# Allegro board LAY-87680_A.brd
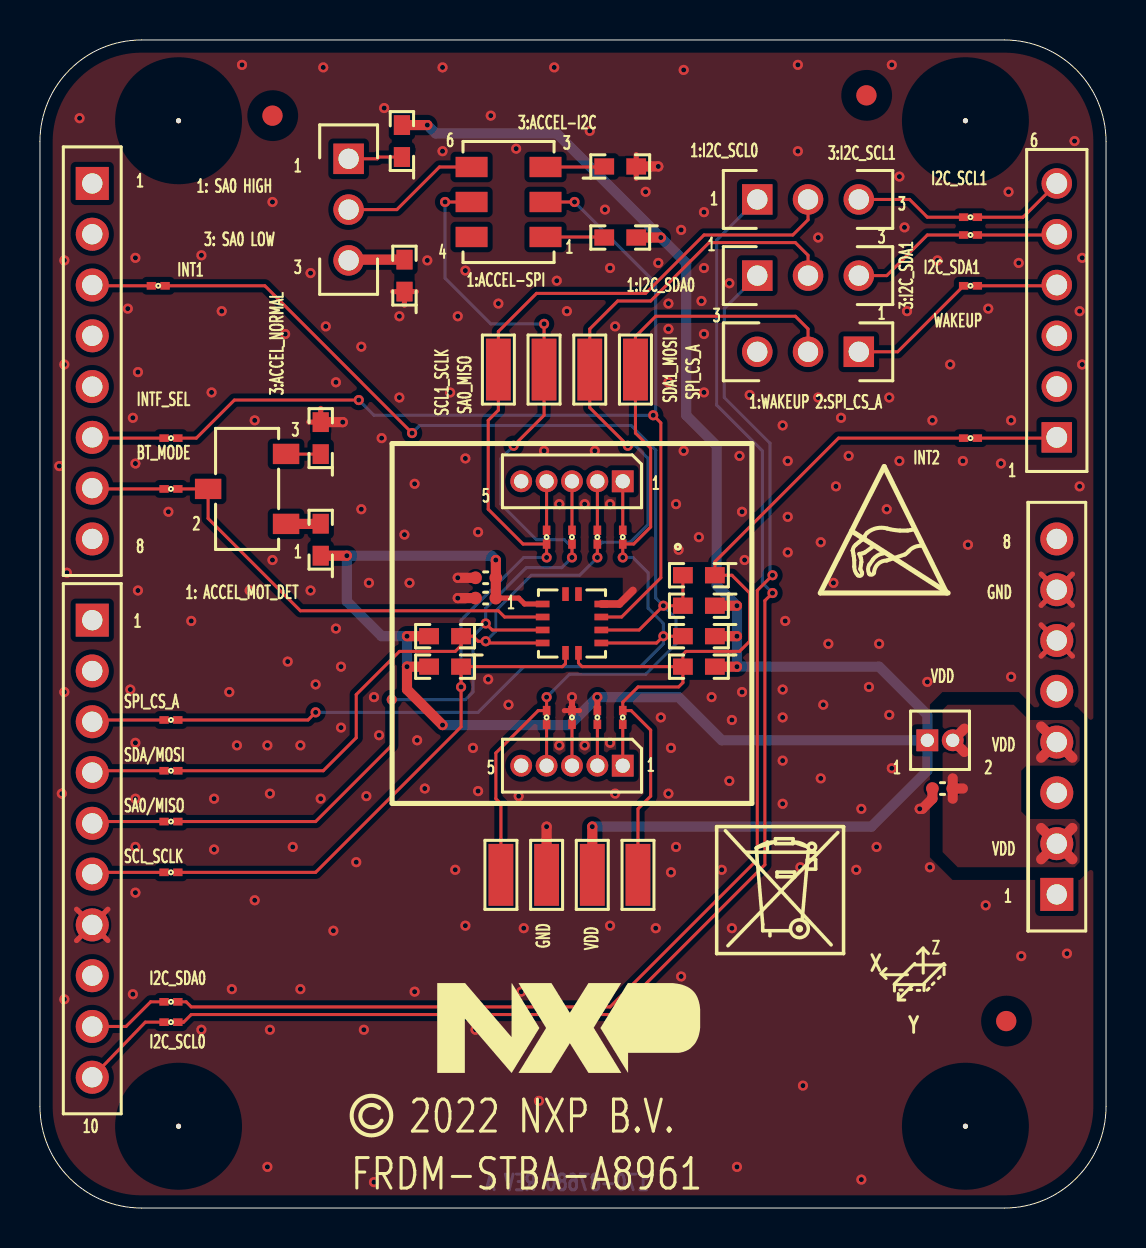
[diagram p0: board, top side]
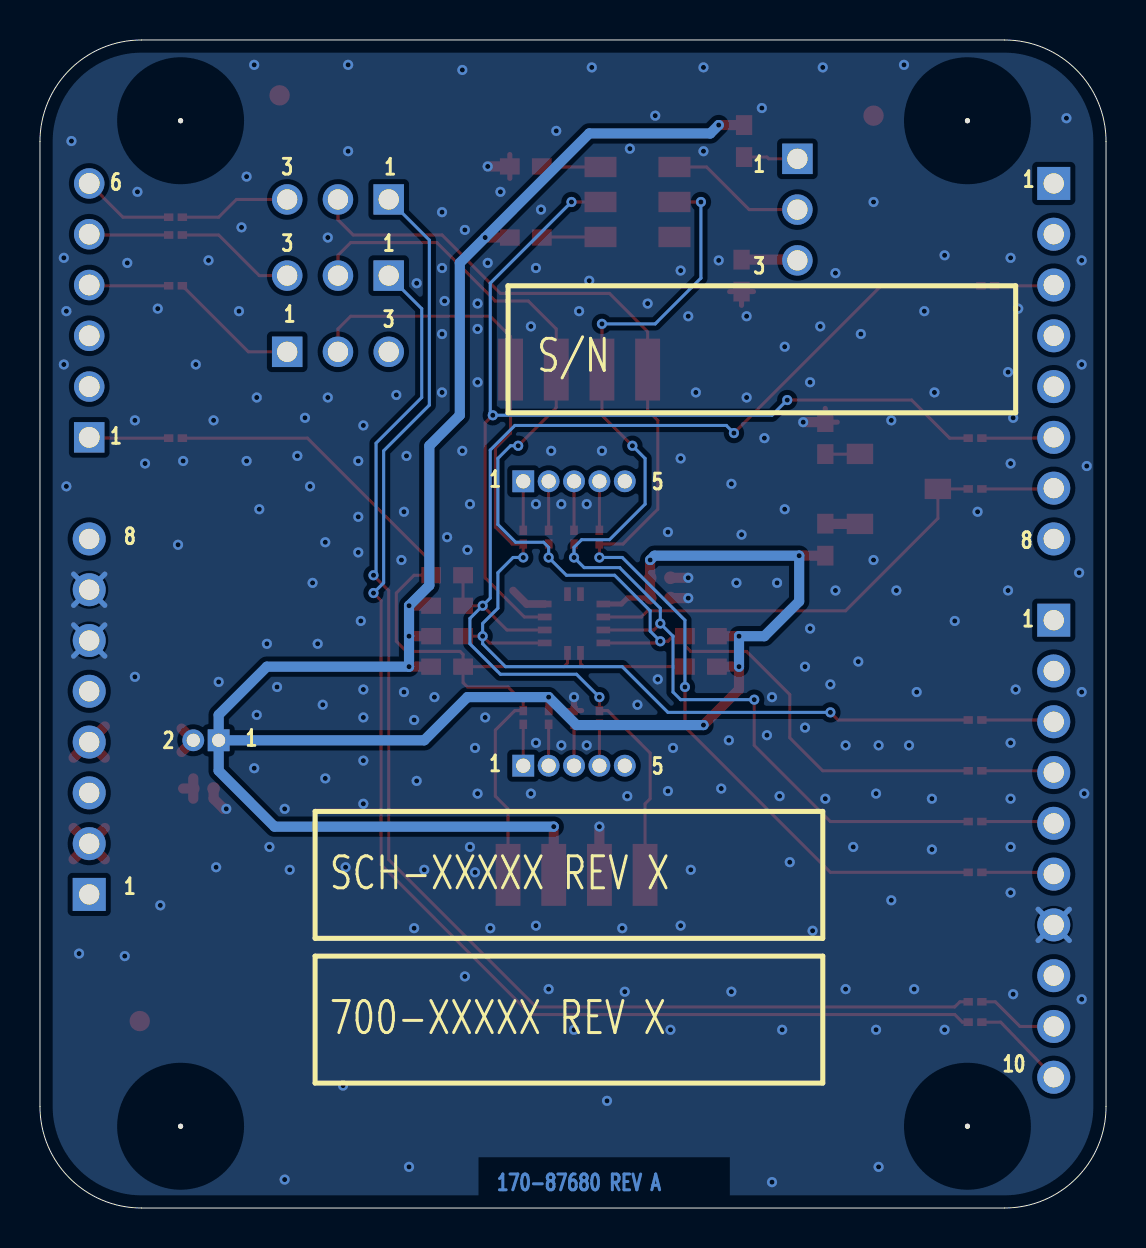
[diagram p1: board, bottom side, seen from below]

Outline 53.34 x 58.42 mm; copper layers: TOP, BOTTOM. Coordinates in mm from the lower left corner of the outline.
Outline path: 0,53.34 0,5.08 arc(1.49,1.49) 5.08,0 48.26,0 arc(51.85,1.49) 53.34,5.08 53.34,53.34 arc(51.85,56.93) 48.26,58.42 5.08,58.42 arc(1.49,56.93) 0,53.34

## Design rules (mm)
constraint set DEFAULT: min track width 0.152
net group BT_MODE: nets BT_MODE N16720548
net group I2C_SCL0: nets I2C_SCL0 N00628
net group I2C_SCL1: nets I2C_SCL1 N05692
net group I2C_SDA0: nets I2C_SDA0 N00622
net group I2C_SDA1: nets I2C_SDA1 N05729
net group INTF_SEL: nets INTF_SEL N16720544
net group WAKEUP: nets N16721741 WAKEUP
net group INT2: nets INT1 INT2 N16659634 N16701284 N16711839 N16711845
net group SA0_MISO: nets N16652885 N16711875 SA0_MISO
net group SCL1_SCLK: nets N16652889 N16711877 SCL1_SCLK
net group SDA1_MOSI: nets N16652859 N16711873 SDA1_MOSI
net group SPI_CS_A: nets N16653001 N16711871 SPI_CS_A

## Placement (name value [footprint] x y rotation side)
C4  0.1UF  [CC0402_25]  22.3 30.51 180 top
C5  1.0UF  [CC0402_25]  22.3 31.52 180 top
C16  2.2UF  [CC0402_25]  45.16 20.98 180 top
INT1  0805  [TESTPOINT_122X049MIL]  23.06 16.66 90 top
INT2  0805  [TESTPOINT_122X049MIL]  29.92 16.66 90 top
J1  HDR 1X5  [HDR1X5_50_TH]  29.16 36.35 0 top
J2  HDR 1X5  [HDR1X5_50_TH]  29.16 22.12 0 top
J3  SKT_1X8  [CON_SKT1X8_TH]  2.62 51.24 0 top
J4  SKT_1X6  [CON_SKT1X6_TH]  50.88 38.54 180 top
J5  SKT_1X10  [CON_SKT1X10_TH]  2.62 29.4 0 top
J6  SKT_1X8  [CON_SKT1X8_TH]  50.88 15.68 180 top
J7  HDR TH 1X3  [HDR103]  35.89 46.63 90 top
J8  HDR TH 1X3  [HDR103]  35.89 50.44 90 top
J9  HDR TH 1X3  [HDR103]  40.97 42.82 270 top
J10  HDR 1X2  [HDR1X2_1P27_TH]  44.4 23.39 180 top
J11  HDR TH 1X3  [HDR103]  15.44 52.48 0 top
NOREF  -  [unnamed]  48.35 9.35 180 top
NOREF#2  -  [unnamed]  11.63 54.64 180 top
NOREF#3  -  [#2]  -142.22 -0.67 0 top
NOREF#4  -  [#2]  44.4 23.39 0 top
NOREF#5  -  [#2]  -142.22 0.62 90 top
NOREF#6  -  [#2]  -125.2 -14.62 90 top
NOREF#7  -  [#2]  -125.2 5.7 90 top
NOREF#8  -  [#2]  6.45 2.61 0 top
NOREF#9  -  [#2]  -142.22 1.87 0 top
NOREF#10  -  [#2]  -142.22 5.7 90 top
NOREF#11  -  [#2]  -132.38 2.56 90 top
NOREF#12  -  [unnamed]  46.3 54.38 0 top
NOREF#13  -  [#2]  27.89 36.35 0 top
NOREF#14  -  [#2]  52.79 55.63 0 top
NOREF#15  -  [#2]  -131.61 2.84 90 top
NOREF#16  -  [#2]  -125.2 6.95 0 top
NOREF#17  -  [#2]  -142.22 -8.29 0 top
NOREF#18  -  [#2]  -142.22 -14.62 90 top
NOREF#19  -  [#2]  -125.2 -12.08 90 top
NOREF#20  -  [#2]  -142.22 -1.92 90 top
NOREF#21  -  [#2]  -431.98 245.39 0 top
NOREF#22  -  [#2]  -134.38 2.34 0 top
NOREF#23  -  [#2]  29.17 42.94 0 top
NOREF#24  -  [#2]  -142.22 -9.54 90 top
NOREF#25  -  [#2]  -142.22 4.41 0 top
NOREF#26  -  [#2]  43.74 24.68 0 top
NOREF#27  -  [#2]  23.56 40.94 90 top
NOREF#28  -  [#2]  30.42 40.94 90 top
NOREF#29  -  [#2]  -125.2 -13.37 0 top
NOREF#30  -  [#2]  -125.2 3.16 90 top
NOREF#31  -  [#2]  16.71 20.98 90 top
NOREF#32  -  [unnamed]  41.35 55.65 180 top
NOREF#33  -  [#2]  -142.22 -3.21 0 top
NOREF#34  -  [#2]  16.71 35.2 90 top
NOREF#35  -  [#2]  16.71 35.2 0 top
NOREF#36  -  [#2]  26.88 42.94 0 top
NOREF#37  -  [#2]  -142.22 -7 90 top
NOREF#38  -  [#2]  27.01 17.66 0 top
NOREF#39  -  [#2]  -125.2 -0.67 0 top
NOREF#40  -  [#2]  -131.61 2.84 90 top
NOREF#41  -  [#2]  44.05 7.77 0 top
NOREF#42  -  [#2]  -125.2 0.62 90 top
NOREF#43  -  [#2]  -125.2 -9.54 90 top
NOREF#44  -  [#2]  -131.4 5.34 0 top
NOREF#45  -  [#2]  22.31 42.94 0 top
NOREF#46  -  [#2]  46.48 0 90 top
NOREF#47  -  [#2]  -125.2 -5.75 0 top
NOREF#48  -  [#2]  28.13 40.94 90 top
NOREF#49  -  [unnamed]  6.93 54.38 0 top
NOREF#50  -  [#2]  -131.61 2.84 90 top
NOREF#51  -  [#2]  -125.2 -7 90 top
NOREF#52  -  [#2]  -142.22 -12.08 90 top
NOREF#53  -  [#2]  -142.22 -4.46 90 top
NOREF#54  -  [#2]  -142.22 -10.83 0 top
NOREF#55  -  [#2]  22.44 17.66 0 top
NOREF#56  -  [#2]  17.62 38.24 0 top
NOREF#57  -  [#2]  29.3 17.66 0 top
NOREF#58  -  [#2]  -142.22 6.95 0 top
NOREF#59  -  [#2]  -142.22 -13.37 0 top
NOREF#60  -  [#2]  23.69 15.66 90 top
NOREF#61  -  [#2]  -125.2 1.87 0 top
NOREF#62  -  [#2]  -125.2 -3.21 0 top
NOREF#63  -  [unnamed]  6.93 4.09 0 top
NOREF#64  -  [#2]  17.62 20.24 90 top
NOREF#65  -  [#2]  -142.22 -5.75 0 top
NOREF#66  -  [#2]  30.55 15.66 90 top
NOREF#67  -  [#2]  -125.2 -4.46 90 top
NOREF#68  -  [#2]  39.07 30.76 0 top
NOREF#69  -  [#2]  27.89 22.12 0 top
NOREF#70  -  [#2]  16.71 20.98 0 top
NOREF#71  -  [#2]  25.85 40.94 90 top
NOREF#72  -  [#2]  -25.42 -46.55 0 top
NOREF#73  -  [#2]  -131.38 2.34 90 top
NOREF#74  -  [#2]  19.89 6.76 0 top
NOREF#75  -  [#2]  0 52.62 0 top
NOREF#76  -  [#2]  -125.2 4.41 0 top
NOREF#77  -  [#2]  -134.16 2.84 0 top
NOREF#78  -  [#2]  -125.2 -1.92 90 top
NOREF#79  -  [#2]  -142.22 3.16 90 top
NOREF#80  -  [#2]  24.6 42.94 0 top
NOREF#81  -  [#2]  25.97 15.66 90 top
NOREF#82  -  [#2]  -458.69 -278.74 0 top
NOREF#83  -  [#2]  -133.38 2.56 0 top
NOREF#84  -  [#2]  24.72 17.66 0 top
NOREF#85  -  [#2]  -125.2 -8.29 0 top
NOREF#86  -  [#2]  28.26 15.66 90 top
NOREF#87  -  [#2]  16.59 4.6 0 top
NOREF#88  -  [unnamed]  46.3 4.09 0 top
NOREF#89  -  [#2]  -125.2 -10.83 0 top
NOREF#90  -  [#2]  -133.38 2.56 90 top
NOREF#91  -  [#2]  33.86 12.73 0 top
NOREF#92  -  [#2]  29.92 39.78 180 bottom
NOREF#93  -  [#2]  39.57 6.25 180 bottom
NOREF#94  -  [#2]  39.57 13.49 180 bottom
R1  4.7K  [RC0603]  20.27 27.08 180 top
R3  4.7K  [RC0603]  20.27 28.6 180 top
R4  10K  [RC0603]  32.97 28.6 180 top
R6  10K  [RC0603]  32.97 30.12 180 top
R9  10K  [RC0603]  32.97 27.08 180 top
R10  0  [RC0603]  32.97 31.65 180 top
R19  10K  [RC0603]  14.05 38.51 90 top
R20  10K  [RC0603]  14.05 33.43 90 top
R21  10K  [RC0603]  29.03 52.1 0 top
R24  10K  [RC0603]  29.03 48.54 180 top
R25  10K  [RC0603]  18.11 53.37 90 top
R26  10K  [RC0603]  18.24 46.63 90 top
SH1  0  [SH0201]  25.35 24.54 90 top
SH4  0  [SH0201]  27.89 24.54 90 top
SH5  0  [SH0201]  25.35 33.55 270 top
SH8  0  [SH0201]  29.16 33.55 270 top
SH9  0  [SH0201]  27.89 33.55 270 top
SH10  0  [SH0201]  29.16 24.54 90 top
SH11  0  [SH0201]  26.62 33.55 270 top
SH20  0  [SH0201]  26.62 24.54 90 top
SH21  0  [SH0201]  46.56 49.56 0 top
SH22  0  [SH0201]  5.92 46.13 0 top
SH23  0  [SH0201]  46.56 48.67 0 top
SH27  0  [SH0201]  46.56 38.51 0 top
SH30  0  [SH0201]  6.55 24.41 0 top
SH31  0  [SH0201]  6.55 21.87 0 top
SH32  0  [SH0201]  6.55 19.33 0 top
SH33  0  [SH0201]  6.55 16.79 0 top
SH34  0  [SH0201]  6.55 10.31 0 top
SH35  0  [SH0201]  6.55 9.3 0 top
SH37  0  [SH0201]  6.55 38.51 0 top
SH38  0  [SH0201]  6.55 35.97 0 top
SH39  0  [SH0201]  46.56 46.13 0 top
SW1  CAS-120TB  [SW3_1P75_3X6]  10.36 35.97 90 top
SW2  CAS-220TA  [SW6_1P75_4X5]  23.44 50.32 90 top
TP3  0805  [TESTPOINT_122X049MIL]  27.64 16.66 90 top
TP4  0805  [TESTPOINT_122X049MIL]  25.35 16.66 90 top
TP5  0805  [TESTPOINT_122X049MIL]  22.94 41.94 90 top
TP6  0805  [TESTPOINT_122X049MIL]  27.51 41.94 90 top
TP7  0805  [TESTPOINT_122X049MIL]  29.79 41.94 90 top
TP8  0805  [TESTPOINT_122X049MIL]  25.22 41.94 90 top
U1  FXLS8961AFR3  [QFN12_0P65_3X3]  26.62 29.24 0 top

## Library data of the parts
C4 C5 C16 = CAP_NP
INT1 INT2 TP3-TP8 = TEST_POINT
J1 J2 = CONN_HDR_5X1
J3 J6 = CONN_HDR_8X1
J4 = CONN_HDR_6X1
J5 = CONN_HDR_10X1
J7-J9 J11 = CONN_HDR_3X1
J10 = CONN_HDR_2X1
R1 R3 R4 R6 R9 R10 R19-R21 R24-R26 = RES
SH1 SH4 SH5 SH8-SH11 SH20-SH23 SH27 SH30-SH35 SH37-SH39 = RES_SHORT-2: Tolerance: TOLERANCE; User Part Number: 470-76473
SW1 = SW3_SPDT_SLD
SW2 = SW_SL_DPDT_6P
U1 = FXLS8961AFR3_QFN12

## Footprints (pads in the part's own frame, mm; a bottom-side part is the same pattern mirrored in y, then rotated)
CC0402_25
  round 0.635 smd: 1(-0.508,0) 2(0.508,0)
CON_SKT1X6_TH
  rect 1.524x1.524 hole 1.041: 1(0,0)
  round 1.524 hole 1.041: 2(0,-2.54) 3(0,-5.08) 4(0,-7.62) 5(0,-10.16) 6(0,-12.7)
CON_SKT1X8_TH
  rect 1.651x1.651 hole 1.016: 1(0,0)
  round 1.651 hole 1.016: 2(0,-2.54) 3(0,-5.08) 4(0,-7.62) 5(0,-10.16) 6(0,-12.7) 7(0,-15.24) 8(0,-17.78)
CON_SKT1X10_TH
  rect 1.651x1.651 hole 1.016: 1(0,0)
  round 1.651 hole 1.016: 2(0,-2.54) 3(0,-5.08) 4(0,-7.62) 5(0,-10.16) 6(0,-12.7) 7(0,-15.24) 8(0,-17.78) 9(0,-20.32) 10(0,-22.86)
HDR1X2_1P27_TH
  rect 1.092x1.092 hole 0.66: 1(0,0)
  round 1.092 hole 0.66: 2(-1.27,0)
HDR1X5_50_TH
  rect 1.092x1.092 hole 0.711: 1(0,0)
  round 1.092 hole 0.711: 2(-1.27,0) 3(-2.54,0) 4(-3.81,0) 5(-5.08,0)
HDR103
  rect 1.524x1.524 hole 1.016: 1(0,0)
  round 1.524 hole 1.016: 2(0,-2.54) 3(0,-5.08)
QFN12_0P65_3X3
  rect 0.686x0.33 smd: 1(-1.468,0.975) 2(-1.468,0.325) 3(-1.468,-0.325) 4(-1.468,-0.975) 7(1.468,-0.975) 8(1.468,-0.325) 9(1.468,0.325) 10(1.468,0.975)
  rect 0.33x0.686 smd: 5(-0.325,-1.468) 6(0.325,-1.468) 11(0.325,1.468) 12(-0.325,1.468)
RC0603
  rect 0.991x0.813 smd: 1(-0.8,0) 2(0.8,0)
SH0201
  rect 0.47x0.381 smd: 1(-0.343,0) 2(0.343,0)
SW3_1P75_3X6
  rect 1.016x1.321 smd: 1(-1.75,-1.95) 2(0,1.95) 3(1.75,-1.95)
SW6_1P75_4X5
  rect 1.016x1.6 smd: 1(-1.75,-1.85) 2(0,-1.85) 3(1.75,-1.85) 4(-1.75,1.85) 5(0,1.85) 6(1.75,1.85)
TESTPOINT_122X049MIL
  rect 3.099x1.245 smd: 1(0,0)
unnamed
  round 1.016 smd: (0,0)

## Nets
GND: C4.2 C5.2 C16.2 J5.7 J6.6 J6.7 R19.2 R21.2 R26.1 SH20.2 TP4.1 U1.10
VDD: C4.1 C5.1 J10.1 R1.2 R3.2 R4.1 R6.1 R9.1 R20.1 R24.1 R25.2 SH4.2 TP3.1 U1.1
BT_MODE: SH38.2 SW1.2 U1.2
I2C_SCL0: J8.1 SH35.2
I2C_SCL1: J8.3 SH21.1
I2C_SDA0: J7.1 SH34.2
I2C_SDA1: J7.3 SH23.1
INT1: INT1.1 R6.2 R10.2 SH1.2 SH22.2 U1.8
INT2: INT2.1 R9.2 R10.1 SH10.2 SH27.1 U1.6
INTF_SEL: SH37.2 SW2.2 U1.9
SA0_MISO: SH11.2 SH32.2 SW2.5(\COM2\) TP8.1 U1.3
SCL1_SCLK: J8.2 R1.1 SH5.2 SH33.2 TP5.1 U1.5
SDA1_MOSI: J7.2 R3.1 SH9.2 SH31.2 TP6.1 U1.4
SPI_CS_A: J9.2 R4.2 SH8.2 SH30.2 TP7.1 U1.7(\\\S\\P\\I\\_\\C\\S\\/WAKE_UP\)
WAKEUP: J9.1 SH39.1
N00622: J5.9 SH34.1
N00628: J5.10 SH35.1
N00993: C16.1 J6.2 J6.4 J10.2
N05692: J4.6 SH21.2
N05729: J4.5 SH23.2
N16652859: J5.4 SH31.1
N16652885: J5.5 SH32.1
N16652889: J5.6 SH33.1
N16653001: J5.3 SH30.1
N16659634: J4.1 SH27.2
N16701284: J3.3 SH22.1
N16711839: J2.1 SH10.1
N16711841: J2.2 SH4.1
N16711843: J2.3 SH20.1
N16711845: J2.4 SH1.1
N16711871: J1.1 SH8.1
N16711873: J1.2 SH9.1
N16711875: J1.3 SH11.1
N16711877: J1.4 SH5.1
N16715705: R20.2 SW1.1
N16718521: R21.1 SW2.3
N16718681: R24.2 SW2.1
N16720544: J3.6 SH37.1
N16720548: J3.7 SH38.1
N16721741: J4.4 SH39.2
N16750160: J11.2 SW2.6
N16750243: J11.1 R25.1
N16750529: J11.3 R26.2
N16884640: R19.1 SW1.3

Pads without a net: J1 5; J2 5; J3 1 2 4 5 8; J4 2 3; J5 1 2 8; J6 1 3 5 8; J9 3; SW2 4; U1 11 12

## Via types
v1: diameter 0.508, hole 0.254, TOP to BOTTOM, 252 vias

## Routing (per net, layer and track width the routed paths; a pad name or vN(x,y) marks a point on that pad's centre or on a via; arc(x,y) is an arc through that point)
GND: length 41.9
  TOP w0.254: 1.83,14.94 J5.7 ; J5.7 1.83,13.38 ; J5.7 3.4,13.38 ; J5.7 3.4,14.94 ; 50.09,27.6 J6.6 ; J6.6 51.66,27.6 ; J6.6 51.66,29.17 ; J6.6 50.09,29.17 ; 27,24.88 SH20.2 26.24,24.88 ; 13.45,39.31 R19.2 14.05,39.99 ; 50.09,30.14 J6.7 ; J6.7 51.66,31.71 ; J6.7 50.09,31.71 ; J6.7 51.66,30.14 ; 17.64,45.83 R26.1 ; R26.1 18.24,45.15 ; R26.1 18.83,45.83 ; 29.83,52.69 R21.2 29.83,51.5
  TOP w0.305: SH20.2 v1(26.62,25.55)
  TOP w0.381: 29.67,30.89 28.99,30.21 U1.10
  TOP w0.508: TP4.1 v1(25.35,19.08) ; C5.2 v1(20.9,31.52) ; v1(44.02,19.96) 44.15,19.96 44.65,20.47 44.65,20.98 ; C4.2 v1(20.9,30.51) ; R21.2 v1(30.94,52.1) ; R19.2 v1(15.15,39.31)
  BOTTOM w0.254: J6.7 51.66,31.71 ; J6.7 51.66,30.14 ; J6.7 50.09,31.71 ; J6.7 50.09,30.14 ; 1.83,14.94 J5.7 ; J5.7 3.4,14.94 ; J5.7 1.83,13.38 ; J5.7 3.4,13.38 ; J6.6 51.66,29.17 ; J6.6 50.09,27.6 ; J6.6 50.09,29.17 ; J6.6 51.66,27.6
  vias: v1(0.97,37.11) v1(1.09,20.73) v1(1.22,47.4) v1(1.22,42.19) v1(1.22,25.81) v1(1.22,10.44) v1(1.35,31.78) v1(1.98,54.51) v1(4.39,44.98) v1(4.52,25.93) v1(4.65,39.52) v1(4.65,10.69) v1(4.78,47.52) v1(4.78,37.24) v1(4.78,23.27) v1(4.78,20.47) v1(4.78,18.06) v1(4.78,15.77) v1(4.9,41.81) v1(4.9,30.89) v1(6.43,34.82) v1(7.57,29.36) v1(8.08,47.65) v1(8.08,8.92) v1(8.59,40.79) v1(8.71,20.47) v1(8.71,17.93) v1(9.09,44.86) v1(9.47,25.81) v1(9.6,10.95) v1(9.86,23.14) v1(10.11,57.18) v1(10.49,30.89) v1(10.74,39.4) v1(10.74,15.39) v1(11.38,23.14) v1(11.38,2.06) v1(11.51,20.73) v1(11.51,8.92) v1(11.63,50.32) v1(11.63,32.41) v1(12.27,43.71) v1(12.4,27.33) v1(12.65,18.06) v1(13.03,23.14) v1(13.03,10.95) v1(13.54,46.76) v1(13.54,30.89) v1(13.79,26.19) v1(14.05,20.47) v1(14.17,57.05) v1(14.3,44.09) v1(14.68,13.87) v1(14.81,41.3) v1(14.81,28.98) v1(15.06,27.08) v1(15.06,24.03) v1(15.82,17.3) v1(16.08,43.08) v1(16.08,34.95) v1(16.21,8.92) v1(16.33,20.6) v1(16.46,31.27) v1(16.71,25.55) v1(16.71,1.3) v1(16.97,23.65) v1(17.09,38.51) v1(17.22,55.02) v1(17.98,44.6) v1(17.98,40.54) v1(18.24,33.68) v1(18.49,31.27) v1(18.75,36.22) v1(18.75,10.82) v1(18.87,23.39) v1(19.25,20.98) v1(19.38,47.4) v1(20.14,57.05) v1(20.14,52.86) v1(20.52,40.79) v1(20.78,16.92) v1(20.9,44.6) v1(21.29,46.89) v1(21.29,37.49) v1(21.29,14.12) v1(21.67,23.01) v1(21.79,8.92) v1(21.92,33.81) v1(21.92,20.85) v1(22.43,26.44) v1(22.56,54.64) v1(22.94,45.24) v1(23.44,25.17) v1(23.83,52.98) v1(23.95,20.6) v1(24.08,10.82) v1(24.21,14) v1(24.97,5.36) v1(25.22,37.87) v1(25.73,57.05) v1(25.86,46.38) v1(25.98,35.2) v1(25.98,23.14) v1(26.37,44.86) v1(26.62,8.92) v1(27.25,35.2) v1(27.25,23.14) v1(27.51,53.87) v1(27.76,37.87) v1(27.89,10.95) v1(28.27,49.94) v1(28.52,47.02) v1(28.52,35.2) v1(28.52,23.27) v1(28.52,14.12) v1(28.78,44.09) v1(28.78,20.73) v1(30.3,50.83) v1(30.81,14) v1(30.94,47.27) v1(31.06,24.54) v1(31.45,45.24) v1(31.45,43.97) v1(31.45,41.3) v1(31.45,20.73) v1(31.57,23.01) v1(31.57,16.79) v1(31.83,35.2) v1(31.83,18.06) v1(31.95,32.92) v1(32.08,48.92) v1(32.08,11.58) v1(32.21,56.92) v1(32.21,37.87) v1(32.97,33.55) v1(33.1,45.36) v1(33.22,49.81) v1(33.22,47.02) v1(33.22,43.71) v1(33.22,40.79) v1(33.6,25.55) v1(34.11,16.92) v1(34.49,46.25) v1(34.49,21.36) v1(34.62,24.41) v1(34.62,14) v1(34.87,2.06) v1(35,37.62) v1(35.13,34.82) v1(35.13,25.81) v1(35.26,32.41) v1(35.51,40.67) v1(37.16,39.14) v1(37.16,25.93) v1(37.16,24.54) v1(37.16,22.38) v1(37.16,20.22) v1(37.29,29.36) v1(37.41,37.36) v1(37.41,34.57) v1(37.41,32.79) v1(37.92,57.18) v1(37.92,52.86) v1(38.05,17.04) v1(38.18,6.12) v1(38.94,48.54) v1(38.94,40.54) v1(39.07,33.3) v1(39.07,21.49) v1(39.19,25.17) v1(39.45,28.22) v1(39.7,31.27) v1(39.83,36.09) v1(40.08,39.52) v1(40.46,37.62) v1(40.84,16.92) v1(41.1,19.96) v1(41.1,1.42) v1(41.48,26.06) v1(41.86,18.06) v1(41.99,28.22) v1(42.37,34.95) v1(42.49,40.54) v1(42.49,24.66) v1(42.62,57.18) v1(42.62,22) v1(43,51.59) v1(43,37.36) v1(43.26,49.05) v1(43.38,44.86) v1(44.4,26.31) v1(44.53,17.04) v1(44.65,39.4) v1(44.91,47.4) v1(45.54,42.19) v1(46.18,37.36) v1(46.43,33.17) v1(47.32,15.14) v1(47.45,44.98) v1(48.08,37.24) v1(48.46,50.83) v1(48.59,39.4) v1(48.59,26.57) v1(48.97,47.27) v1(49.1,12.6) v1(51.38,12.73) v1(51.77,53.37) v1(52.02,44.86) v1(52.02,36.09) v1(52.15,47.52) v1(52.15,42.19)
VDD: length 129.6
  TOP w0.254: U1.1 24.25,30.21 23.95,30.51 C4.1
  TOP w0.305: SH4.2 v1(27.89,25.55)
  TOP w0.508: R4.1 v1(34.87,28.6) ; R1.2 v1(18.36,27.08) 18.36,25.93 v1(20.14,24.16) ; R9.1 v1(34.87,27.08) ; R25.2 v1(19.38,54.17) ; R20.1 v1(15.35,32.63) ; R24.1 v1(31.06,48.54) ; R3.2 v1(18.36,28.6) ; TP3.1 v1(27.64,19.08) ; v1(22.81,32.41) C5.1 C4.1 ; R6.1 v1(34.87,30.12)
  BOTTOM w0.508: v1(18.36,27.08) v1(18.36,28.6) 17.09,28.6 15.35,30.34 v1(15.35,32.63) 22.59,32.63 v1(22.81,32.41) ; J10.1 44.4,21.87 41.61,19.08 v1(27.64,19.08) ; J10.1 44.4,24.66 41.99,27.08 v1(34.87,27.08) v1(34.87,28.6) v1(34.87,30.12) 33.86,31.14 33.86,38.13 32.33,39.65 32.33,47.27 v1(31.06,48.54) 25.86,53.75 19.8,53.75 v1(19.38,54.17) ; J10.1 34.11,23.39 31.95,25.55 v1(27.89,25.55) 26.49,24.16 v1(20.14,24.16)
BT_MODE: length 21.8
  TOP w0.152: U1.2 23.25,29.56 22.94,29.87 13.03,29.87 8.41,34.49 SW1.2 SH38.2
I2C_SCL0: length 68.1
  TOP w0.152: v1(36.65,30.76) 36.27,30.38 36.27,17.17 28.78,9.68 7.57,9.68 7.19,9.3 SH35.2
  BOTTOM w0.152: v1(36.65,30.76) 36.14,31.27 36.14,37.87 33.86,40.16 33.86,48.41 J8.1
I2C_SCL1: length 5.6
  TOP w0.152: J8.3 43.51,50.44 44.4,49.56 SH21.1
I2C_SDA0: length 63.4
  TOP w0.152: SH34.2 7.32,10.31 7.57,10.06 28.52,10.06 35.89,17.42 35.89,30.89 v1(36.65,31.65)
  BOTTOM w0.152: J7.1 34.24,44.98 34.24,40.54 36.53,38.25 36.53,31.78 v1(36.65,31.65)
I2C_SDA1: length 6.1
  TOP w0.152: SH23.1 44.4,48.67 42.37,46.63 J7.3
INT1: length 62.4
  TOP w0.152: SH22.2 11.25,46.13 v1(18.62,38.76) ; U1.8 29.98,28.91 v1(31.19,30.12) R6.2 R10.2 ; v1(25.35,25.55) SH1.2 24.93,24.88 22.81,22.76 22.81,20.47 23.06,20.22 INT1.1
  BOTTOM w0.152: v1(18.62,38.76) 19,39.14 29.58,39.14 30.81,37.91 30.81,30.51 v1(31.19,30.12) 31.83,29.49 31.83,28.22 30.3,26.7 26.49,26.7 v1(25.35,25.55)
INT2: length 44.2
  TOP w0.152: R9.2 32.17,27.69 32.32,27.84 35,27.84 35.51,28.35 35.51,30.76 34.62,31.65 R10.1 33.77,32.32 39.95,38.51 SH27.1 ; R9.2 32.17,26.28 31.95,26.06 29.92,26.06 29.16,25.3 SH10.2 29.58,24.88 30.56,23.9 30.56,20.6 29.92,19.96 INT2.1 ; R9.2 27.13,27.08 26.94,27.26 U1.6
INTF_SEL: length 50.8
  TOP w0.152: U1.9 29.1,29.56 31.06,31.52 31.06,39.27 v1(30.68,39.65) ; SW2.2 v1(26.75,50.32) ; v1(15.95,40.41) 9.73,40.41 7.82,38.51 SH37.2
  BOTTOM w0.152: v1(15.95,40.41) 16.71,39.65 v1(30.68,39.65) 30.81,39.78 30.81,46.25 v1(26.75,50.32)
SA0_MISO: length 58.2
  TOP w0.152: U1.3 22.63,28.91 v1(22.3,29.24) ; SW2.5 v1(20.27,50.32) ; v1(23.7,38.13) 25.22,39.65 TP8.1 v1(25.22,44.22) ; SH32.2 13.79,19.33 17.6,23.14 v1(17.6,25.43) ; SH11.2 v1(26.62,32.54)
  BOTTOM w0.152: v1(25.22,44.22) 22.56,44.22 20.27,46.51 v1(20.27,50.32) ; v1(17.6,25.43) 21.29,25.43 21.67,25.81 21.67,28.6 v1(22.3,29.24) 22.3,30 24.33,32.03 26.11,32.03 v1(26.62,32.54) 26.62,33.05 26.24,33.43 24.84,33.43 23.06,35.2 23.06,37.49 v1(23.7,38.13)
SCL1_SCLK: length 67.2
  TOP w0.152: U1.5 26.29,27.23 26.14,27.08 R1.1 v1(21.07,26.06) 21.07,24.07 13.79,16.79 SH33.2 ; v1(25.35,32.54) SH5.2 24.17,33.21 22.43,34.95 22.43,39.4 22.94,39.9 TP5.1 22.94,43.84 24.84,45.75 30.3,45.75 33.22,48.67 37.67,48.67 38.43,49.43 J8.2
  BOTTOM w0.152: v1(21.07,26.06) 21.07,29.4 24.21,32.54 v1(25.35,32.54)
SDA1_MOSI: length 60
  TOP w0.152: SH31.2 14.17,21.87 15.82,23.52 15.82,25.68 17.98,27.84 20.78,27.84 21.07,28.13 R3.1 21.67,28.6 21.92,28.35 v1(22.3,28.35) 22.39,28.26 U1.4 ; v1(29.41,38.13) 27.51,40.03 TP6.1 27.51,43.97 28.91,45.36 30.56,45.36 33.48,48.29 37.8,48.29 38.43,47.65 J7.2 ; v1(27.89,32.54) SH9.2
  BOTTOM w0.152: v1(29.41,38.13) 29.79,38.13 30.43,37.49 30.43,34.19 29.54,33.3 28.14,33.3 27.89,33.05 v1(27.89,32.54) 27,31.65 24.59,31.65 22.81,29.87 22.81,28.85 v1(22.3,28.35)
SPI_CS_A: length 58.3
  TOP w0.152: J9.2 38.43,43.97 37.8,44.6 30.81,44.6 29.79,43.59 TP7.1 29.79,38.76 30.56,38 30.56,34.06 29.71,33.21 SH8.2 v1(29.16,32.54) ; U1.7 30.85,28.26 v1(31.19,28.6) R4.2 ; SH30.2 13.41,24.41 v1(13.79,24.79)
  BOTTOM w0.152: v1(29.16,32.54) 29.67,32.54 30.43,31.78 30.43,30 31.19,29.24 v1(31.19,28.6) 31.19,28.22 30.05,27.08 24.21,27.08 21.92,24.79 v1(13.79,24.79)
WAKEUP: length 6.6
  TOP w0.152: J9.1 42.91,42.82 SH39.1
N00622: length 4.1
  TOP w0.152: SH34.1 5.54,10.31 4.31,9.08 J5.9
N00628: length 4.8
  TOP w0.152: J5.10 5.27,9.3 SH35.1
N00993: length 10.9
  TOP w0.508: 50.09,19.01 J6.2 ; J6.2 50.09,17.44 ; J6.2 51.66,19.01 ; J6.2 51.66,17.44 ; 46.25,23.98 J10.2 46.25,22.81 ; 50.09,22.52 J6.4 ; J6.4 51.66,22.52 ; J6.4 50.09,24.09 ; C16.1 46.18,20.98 ; C16.1 45.67,20.47 ; C16.1 45.67,21.49
N05692: length 4.7
  TOP w0.152: J4.6 49.19,49.56 SH21.2
N05729: length 4
  TOP w0.152: J4.5 50.84,48.67 SH23.2
N16652859: length 3.7
  TOP w0.152: SH31.1 2.6,21.87 J5.4
N16652885: length 3.7
  TOP w0.152: J5.5 2.6,19.33 SH32.1
N16652889: length 3.7
  TOP w0.152: SH33.1 2.6,16.79 J5.6
N16653001: length 3.7
  TOP w0.152: SH30.1 2.6,24.41 J5.3
N16659634: length 4
  TOP w0.152: J4.1 50.84,38.51 SH27.2
N16701284: length 3.1
  TOP w0.152: J3.3 2.55,46.13 SH22.1
N16711839: length 2.1
  TOP w0.152: SH10.1 J2.1
N16711841: length 2.1
  TOP w0.152: SH4.1 J2.2
N16711843: length 2.1
  TOP w0.152: SH20.1 26.62,22.12
N16711845: length 2.1
  TOP w0.152: SH1.1 J2.4
N16711871: length 2.5
  TOP w0.152: SH8.1 J1.1
N16711873: length 2.5
  TOP w0.152: SH9.1 J1.2
N16711875: length 2.5
  TOP w0.152: SH11.1 26.62,36.35
N16711877: length 2.5
  TOP w0.152: SH5.1 J1.4
N16715705: length 1.7
  TOP w0.508: SW1.1 14.04,34.22 R20.2
N16718521: length 2.9
  TOP w0.152: R21.1 28.2,52.07 SW2.3
N16718681: length 2.9
  TOP w0.152: SW2.1 28.2,48.57 R24.2
N16720544: length 3.7
  TOP w0.152: SH37.1 2.55,38.51 J3.6
N16720548: length 3.7
  TOP w0.152: J3.7 2.55,35.97 SH38.1
N16721741: length 4
  TOP w0.152: J4.4 50.84,46.13 SH39.2
N16750160: length 7
  TOP w0.152: J11.2 17.86,49.94 19.99,52.07 SW2.6
N16750243: length 2.7
  TOP w0.152: R25.1 16.97,52.57 16.88,52.48 J11.1
N16750529: length 2.8
  TOP w0.508: J11.3 15.48,47.43 R26.2
N16884640: length 1.7
  TOP w0.152: SW1.3 12.32,37.71 R19.1

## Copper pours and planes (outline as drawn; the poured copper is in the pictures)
GND on TOP: 5.08,0.64 1.94,1.94 0.64,5.08 0.64,53.34 1.94,56.48 5.08,57.78 48.26,57.78 51.4,56.48 52.7,53.34 52.7,5.08 51.4,1.94 48.26,0.64 ; 7 cut-outs
GND on BOTTOM: 5.08,0.64 1.94,1.94 0.64,5.08 0.64,53.34 1.94,56.48 5.08,57.78 48.26,57.78 51.4,56.48 52.7,53.34 52.7,5.08 51.4,1.94 48.26,0.64 ; 1 cut-out
N00993 on TOP: 45.16,24.92 45.16,17.81 45.92,17.04 51.77,17.04 52.02,17.3 52.02,19.2 51.77,19.46 49.48,19.46 49.1,19.84 49.1,21.87 49.35,22.12 51.77,22.12 52.02,22.38 52.02,24.03 51.64,24.41 49.48,24.41 48.72,25.17 45.42,25.17

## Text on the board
BOTTOM: 170-87680 REV A | 5 of 8 | L2_SS
Board Geometry/Soldermask Bottom: 6 OF 8 | SECONDARY SOLDERMASK
Ref Des/Silkscreen Bottom: 7 OF 8 | SECONDARY SILKSCREEN
User.Comments: 17 | 1 OF 1 | TEST PROBE | 1/1 | 1
TOP: 4 OF 8 | L1_PS
Board Geometry/Soldermask Top: 3 OF 8 | PRIMARY SOLDERMASK
Ref Des/Silkscreen Top: SPI_CS_A | SDA/MOSI | SA0/MISO | SCL_SCLK | INTF_SEL | BT_MODE | I2C_SDA0 | I2C_SCL0 | INT1 | INT2 | I2C_SDA1 | I2C_SCL1 | Z | WAKEUP | GND | VDD | 3: SA0 LOW | 3:ACCEL-I2C | 3:I2C_SCL1 | 3:ACCEL_NORMAL | 3:I2C_SDA1 | X | Y | 2 OF 8 | PRIMARY SILKSCREEN | FRDM-STBA-A8961
XSECTION_CHART: ORANGE COLOR, BOTH SIDES. MODIFICATION OF SOLDERMASK IS NOT ALLOWED WITHOUT WRITTEN PERMISSION FROM NXP. | *  SURFACE - AIR 0 MIL | *  DIELECTRIC - DRY_FILM_MASK 0.7 MIL | L1 TOP CONDUCTOR - 1/2OZ_COPPER_PLATED_FOIL 2.1 MIL | *  DIELECTRIC - FR-4 56.4 MIL | L2 BOTTOM CONDUCTOR - 1/2OZ_COPPER_PLATED_FOIL 2.1 MIL | DESIGN CROSS SECTION CHART | ___________________________ | TOTAL THICKNESS 62 MIL | 1-2 | INTENTIONAL 21 SHORTS AT: | Location           RefDes      Net 1         Net 2 | (-40.00 1655.00)   SH22      N16701284  &  INT1 | (-15.00 205.00)    SH35      N00628     &  I2C_SCL0 | (-15.00 245.00)    SH34      N00622     &  I2C_SDA0 | (-15.00 500.00)    SH33      N16652889  &  SCL1_SCLK | (-15.00 800.00)    SH30      N16653001  &  SPI_CS_A | (-15.00 700.00)    SH31      N16652859  &  SDA1_MOSI | (-15.00 600.00)    SH32      N16652885  &  SA0_MISO | (-15.00 1355.00)   SH37      N16720544  &  INTF_SEL | (-15.00 1255.00)   SH38      N16720548  &  BT_MODE | (725.00 805.00)    SH1       N16711845  &  INT1 | (725.00 1160.00)   SH5       N16711877  &  SCL1_SCLK | (875.00 805.00)    SH10      N16711839  &  INT2 | (775.00 805.00)    SH20      N16711843  &  GND | (825.00 805.00)    SH4       N16711841  &  VDD | (825.00 1160.00)   SH9       N16711873  &  SDA1_MOSI | (875.00 1160.00)   SH8       N16711871  &  SPI_CS_A | (775.00 1160.00)   SH11      N16711875  &  SA0_MISO | (1560.00 1355.00)  SH27      INT2       &  N16659634 | (1560.00 1655.00)  SH39      WAKEUP     &  N16721741 | (1560.00 1755.00)  SH23      I2C_SDA1   &  N05729 | (1560.00 1790.00)  SH21      I2C_SCL1   &  N05692 | 19 | 16
DIMENSION: PRIMARY DATUM GRID ORIGIN
BODY_CENTER: 1 OF 8 | PASTEMASK TOP
DISPLAY_TOP: 8 OF 8 | SECONDARY PASTEMASK
User.16: FIGURE | FINISHED_SIZE | 10.0 | 26.0 | 28.0 | 40.0 | 41.0 | 125.0 | DRILL CHART: TOP to BOTTOM | ALL UNITS ARE IN MILS | TOLERANCE_DRILL | +0.0/-10.0 | +2.0/-2.0 | +3.0/-3.0 | PLATED | NON-PLATED | QTY | 252 | 2 | 10 | 38 | 6 | 4
